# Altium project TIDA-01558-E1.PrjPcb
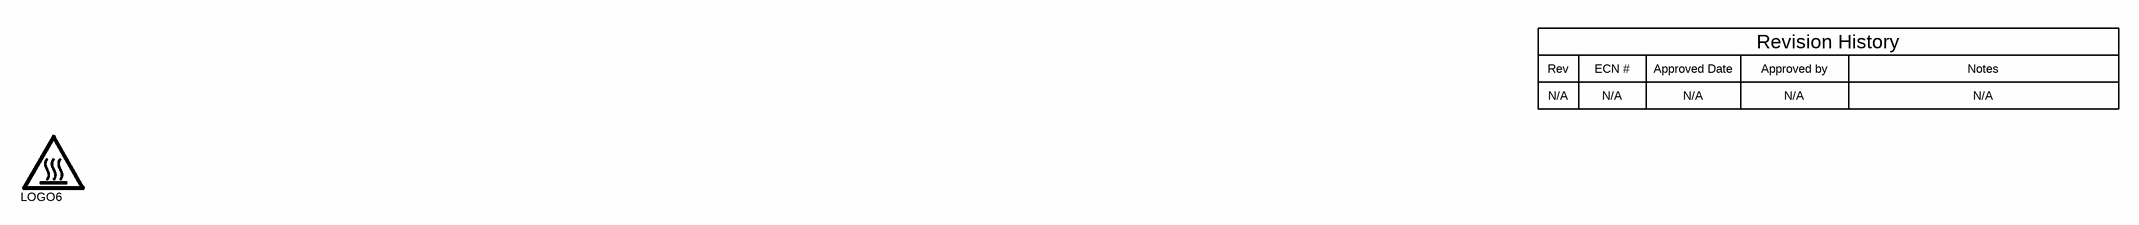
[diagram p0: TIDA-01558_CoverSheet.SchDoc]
CopyrightYear: 2017; EVM_Orderable: N/A; PCB_Layout: Akshay Labhe; PCB_Rev: E1; PRJ_Customer: Public Release; PRJ_Engineer: Neha Nain; PRJ_Number: TIDA-01558; PRJ_Title: 500W Buck Boost; SCH_Rev: E1; TechSupport: http://www.ti.com/support; TID: TIDA-01558
3 sheets, 86 parts. Net scope: flat (ports and power ports of the same name join across sheets).
Board file: TIDA-01558_PCB.PcbDoc
Sheets:
  TIDA-01558_CoverSheet.SchDoc
  TIDA-01558_Sheet1.SchDoc
  TIDA-01558_Hardware.SchDoc

## Sheet TIDA-01558_CoverSheet.SchDoc: Cover Sheet
size 431 x 279 mm; Date: Not shown in title block; ApprovedBy: Not shown in title block; CheckedBy: Not shown in title block; Author: Not shown in title block; CompanyName: Not shown in title block; DrawnBy: Neha Nain; Engineer: Not shown in title block; Organization: Not shown in title block; Address1: Not shown in title block; Address2: Not shown in title block; Address3: Not shown in title block; Address4: Not shown in title block; DocumentNumber: 1; Revision: Use project parameter SCH_Rev; SheetNumber: 1; SheetTotal: 3; PageSetup: Record=PageOptions¦CenterHorizontal=True¦CenterVertical=True¦PrintScale=1.00¦XCorrection=1.00¦YCorrection=1.00¦PrintKind=0¦BorderSize=5000000¦LeftOffset=0¦BottomOffset=0¦Orientation=2¦PaperLength=1000¦PaperWidth=1000¦Scale=100¦PaperSource=15¦PrintQuality=600¦MediaType=1¦DitherType=10¦PaperKind=Letter¦PrintScaleMode=1

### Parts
(Parts that share a designator on the sheet are numbered #1, #2 ... from top to bottom, then left to right.)
LOGO6#1  CAUTION HOT SURFACE  [IEC_HotSurface_Small]  (value not drawn)  (no BOM)

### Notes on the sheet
- Rev
- N/A
- ECN #
- Approved Date
- Approved by
- Revision History
- Notes

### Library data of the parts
LOGO6#1 = IEC_HotSurface: IEC 61010-1 Hot Surface Warning; SymbolCreator: a0412235

## Sheet TIDA-01558_Sheet1.SchDoc: Sheet1
size 431 x 279 mm; Date: Not shown in title block; ApprovedBy: Not shown in title block; CheckedBy: Not shown in title block; Author: Not shown in title block; CompanyName: Not shown in title block; DrawnBy: Neha Nain; Engineer: Not shown in title block; Organization: Not shown in title block; Address1: Not shown in title block; Address2: Not shown in title block; Address3: Not shown in title block; Address4: Not shown in title block; DocumentNumber: 1; Revision: Use project parameter SCH_Rev; SheetNumber: 2; SheetTotal: 3; PageSetup: Record=PageOptions¦CenterHorizontal=True¦CenterVertical=True¦PrintScale=1.00¦XCorrection=1.00¦YCorrection=1.00¦PrintKind=0¦BorderSize=5000000¦LeftOffset=0¦BottomOffset=0¦Orientation=2¦PaperLength=1000¦PaperWidth=1000¦Scale=100¦PaperSource=15¦PrintQuality=600¦MediaType=1¦DitherType=10¦PaperKind=Letter¦PrintScaleMode=1
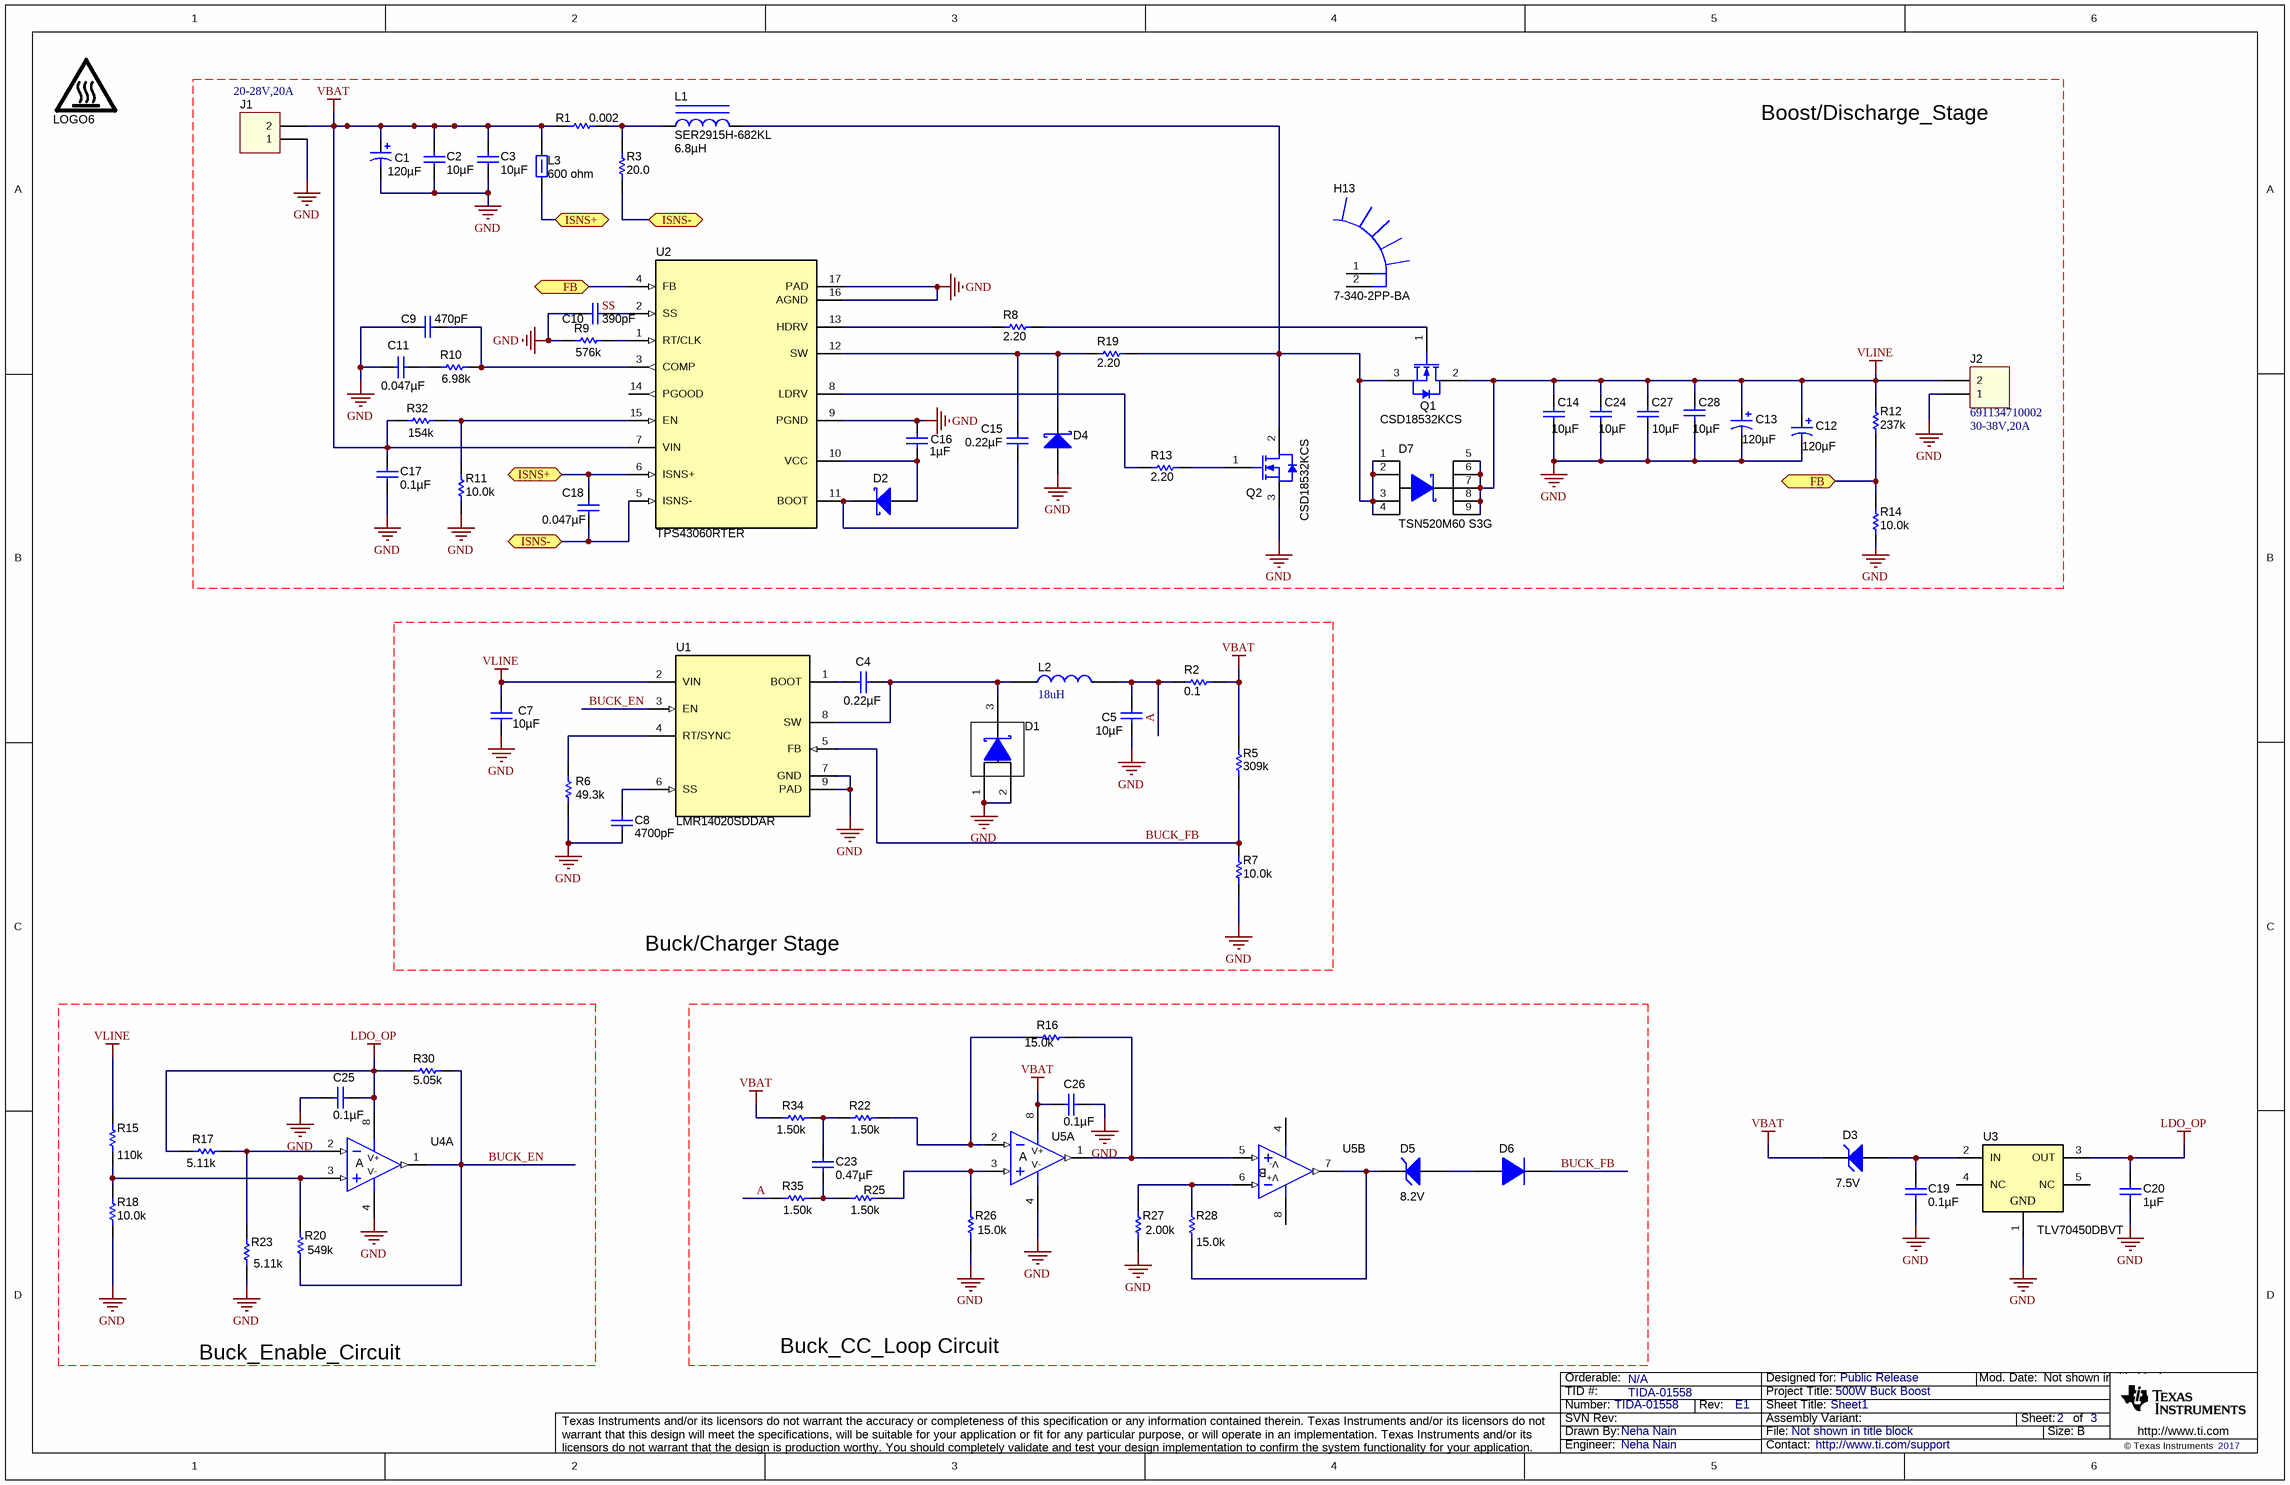
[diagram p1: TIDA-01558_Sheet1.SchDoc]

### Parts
(Parts that share a designator on the sheet are numbered #1, #2 ... from top to bottom, then left to right.)
C1  ValueDisplayed: 120µF  [Chemi-Con_800x1150]  (hidden comment: 127AVG050MFBJ)
C2  ValueDisplayed: 10µF  [1210_280]  (hidden comment: C3225X7R1H106M250AC)
C3  ValueDisplayed: 10µF  [1210_280]  (hidden comment: C3225X7R1H106M250AC)
C4  ValueDisplayed: 0.22µF  [0603]  (hidden comment: 06033D224KAT2A)
C5  ValueDisplayed: 10µF  [1210_280]  (hidden comment: C3225X7R1H106M250AC)
C7  ValueDisplayed: 10µF  [1210_280]  (hidden comment: C3225X7R1H106M250AC)
C8  ValueDisplayed: 4700pF  [0603]  (hidden comment: GRM188R71E472KA01D)
C9  ValueDisplayed: 470pF  [0603]  (hidden comment: C0603C471K3RACTU)
C10  ValueDisplayed: 390pF  [0603]  (hidden comment: 06035A391JAT2A)
C11  ValueDisplayed: 0.047µF  [0603]  (hidden comment: 06033C473JAT2A)
C12  ValueDisplayed: 120µF  [Chemi-Con_800x1150]  (hidden comment: 127AVG050MFBJ)
C13  ValueDisplayed: 120µF  [Chemi-Con_800x1150]  (hidden comment: 127AVG050MFBJ)
C14  ValueDisplayed: 10µF  [1210_280]  (hidden comment: C3225X7R1H106M250AC)
C15  ValueDisplayed: 0.22µF  [0603]  (hidden comment: 06033D224KAT2A)
C16  ValueDisplayed: 1µF  [0603]  (hidden comment: 06033C105KAT2A)
C17  ValueDisplayed: 0.1µF  [0603]  (hidden comment: 06035C104KAT2A)
C18  ValueDisplayed: 0.047µF  [1206]  (hidden comment: GRM31M5C1H473JA01L)
C19  ValueDisplayed: 0.1µF  [0603]  (hidden comment: 06035C104KAT2A)
C20  ValueDisplayed: 1µF  [0603]  (hidden comment: 06033C105KAT2A)
C23  ValueDisplayed: 0.47µF  [0603]  (hidden comment: GRM188R71E474KA12D)
C24  ValueDisplayed: 10µF  [1210_280]  (hidden comment: C3225X7R1H106M250AC)
C25  ValueDisplayed: 0.1µF  [0603]  (hidden comment: 06033C104KAT2A)
C26  ValueDisplayed: 0.1µF  [0603]  (hidden comment: 06033C104KAT2A)
C27  ValueDisplayed: 10µF  [1210_280]  (hidden comment: C3225X7R1H106M250AC)
C28  ValueDisplayed: 10µF  [1210_280]  (hidden comment: C3225X7R1H106M250AC)
D1  MBR10U60-TP  [TO-277A]  (value not drawn)
D2  PMEG6010CEJ,115  [SOD-323F]  (value not drawn)
D3  value 7.5V  [SMA]  (hidden comment: SMAJ5922B-TP)
D4  PMEG6010CEJ,115  [SOD-323F]  (value not drawn)
D5  value 8.2V  [SOD-323]  (hidden comment: MM3Z8V2T1G)
D6  1N4448WX-TP  [SOD-323]  (value not drawn)
D7  TSN520M60 S3G  [PDFN56]
H13  7-340-2PP-BA  [HEATSINK_7-340-2PP]
J1  691134710002  [691134710002]  (value not drawn)
J2  691134710002  [691134710002]
L1  SER2915H-682KL  ValueDisplayed: 6.8µH  [SER2915]
L2  value 18uH  [IND_RLB9012]  (hidden comment: RLB9012-180KL)
L3  ValueDisplayed: 600 ohm  [0603]  (hidden comment: BLM18KG601SN1D)
LOGO6#2  CAUTION HOT SURFACE  [IEC_HotSurface_Small]  (value not drawn)  (no BOM)
Q1  CSD18532KCS  [TO-220AB_Horizontal_100mil]
Q2  CSD18532KCS  [TO-220AB_Horizontal_100mil]
R1  ValueDisplayed: 0.002  [2512]  (hidden comment: CRE2512-FZ-R002E-3)
R2  ValueDisplayed: 0.1  [1206]  (hidden comment: CRM1206-FX-R100ELF)
R3  ValueDisplayed: 20.0  [0603]  (hidden comment: RC0603FR-0720RL)
R5  ValueDisplayed: 309k  [0603]  (hidden comment: RT0603BRD07309KL)
R6  ValueDisplayed: 49.3k  [0603]  (hidden comment: RT0603DRE0749K3L)
R7  ValueDisplayed: 10.0k  [0603]  (hidden comment: ERJ-3EKF1002V)
R8  ValueDisplayed: 2.20  [0805_HV1]  (hidden comment: RC0805FR-072R2L)
R9  ValueDisplayed: 576k  [0603]  (hidden comment: RT0603DRE07576KL)
R10  ValueDisplayed: 6.98k  [0603]  (hidden comment: RT0603DRE076K98L)
R11  ValueDisplayed: 10.0k  [0603]  (hidden comment: ERJ-3EKF1002V)
R12  ValueDisplayed: 237k  [0603]  (hidden comment: RT0603BRD07237KL)
R13  ValueDisplayed: 2.20  [1206]  (hidden comment: ERJ-8RQF2R2V)
R14  ValueDisplayed: 10.0k  [0603]  (hidden comment: ERJ-3EKF1002V)
R15  ValueDisplayed: 110k  [0603]  (hidden comment: RT0603DRE07110KL)
R16  ValueDisplayed: 15.0k  [0603]  (hidden comment: RT0603BRD0715KL)
R17  ValueDisplayed: 5.11k  [0603]  (hidden comment: RG1608P-5111-B-T5)
R18  ValueDisplayed: 10.0k  [0603]  (hidden comment: ERJ-3EKF1002V)
R19  ValueDisplayed: 2.20  [0805_HV1]  (hidden comment: RC0805FR-072R2L)
R20  ValueDisplayed: 549k  [0603]  (hidden comment: RC0603FR-07549KL)
R22  ValueDisplayed: 1.50k  [0603]  (hidden comment: RT0603BRD071K5L)
R23  ValueDisplayed: 5.11k  [0603]  (hidden comment: RG1608P-5111-B-T5)
R25  ValueDisplayed: 1.50k  [0603]  (hidden comment: RT0603BRD071K5L)
R26  ValueDisplayed: 15.0k  [0603]  (hidden comment: RT0603BRD0715KL)
R27  ValueDisplayed: 2.00k  [0603]  (hidden comment: RT0603BRD072KL)
R28  ValueDisplayed: 15.0k  [0603]  (hidden comment: RT0603BRD0715KL)
R30  ValueDisplayed: 5.05k  [0603]  (hidden comment: RT0603BRD075K05L)
R32  ValueDisplayed: 154k  [0603]  (hidden comment: RT0603DRE07154KL)
R34  ValueDisplayed: 1.50k  [0603]  (hidden comment: RT0603BRD071K5L)
R35  ValueDisplayed: 1.50k  [0603]  (hidden comment: RT0603BRD071K5L)
U1  LMR14020SDDAR  [DDA0008E_N]
U2  TPS43060RTER  [RTE0016E]
U3  TLV70450DBVT  [DBV0005A_N]
U4  LM293AD  [D0008A_N]  (value not drawn)  (part A of 2)
U5  LM358AD  [D0008A_N]  (value not drawn)  (parts A,B of 2)

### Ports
FB, ISNS+, ISNS-

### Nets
GND: C1.2(-) C2.2 C3.2 C5.2 C7.2 C8.2 C9.2 C10.2 C11.2 C12.2(-) C13.2(-) C14.2 C16.1 C17.2 C19.2 C20.2 C24.2 C25.2 C26.2 C27.2 C28.2 D1.1(A) D1.2(A) D4.2(A) J1.1 J2.1 Q2.3(S) R6.1 R7.1 R9.1 R11.1 R14.1 R18.1 R23.1 R26.1 R27.1 U1.7(GND) U1.9(PAD) U2.9(PGND) U2.16(AGND) U2.17(PAD) U3.1(GND) U4.4(V-) U5.4(V-)
LDO_OP: C20.1 C25.1 R17.1 R30.1 U3.3(OUT) U4.8(V+)
VBAT: C1.1(+) C2.1 C3.1 C17.1 C26.1 D3.1(K) J1.2 L3.2 R1.1 R2.2 R5.2 R32.1 R34.1 U2.7(VIN) U5.8(V+)
VLINE: C7.1 C12.1(+) C13.1(+) C14.1 C24.1 C27.1 C28.1 D7.5(C) D7.6(C) D7.7(C) D7.8(C) D7.9(C) J2.2 Q1.2(D) R12.2 R15.2 U1.2(VIN)
A: C5.1 L2.2 R2.1 R35.1
BUCK_EN: R20.1 R30.2 U1.3(EN) U4.1(OUT)
BUCK_FB: D6.1(K) R5.1 R7.2 U1.5(FB)
FB: R12.1 R14.2 U2.4(FB) ; port FB
ISNS+: C18.1 L3.1 U2.6(ISNS+) ; port ISNS+
ISNS-: C18.2 R3.1 U2.5(ISNS-) ; port ISNS-
NetC4_1: C4.1 U1.1(BOOT)
NetC4_2: C4.2 D1.3(K) L2.1 U1.8(SW)
NetC8_1: C8.1 U1.6(SS)
NetC9_1: C9.1 R10.2 U2.3(COMP)
NetC10_1: C10.1 U2.2(SS)
NetC11_1: C11.1 R10.1
NetC15_1: C15.1 D4.1(K) R19.1 U2.12(SW)
NetC15_2: C15.2 D2.1(K) U2.11(BOOT)
NetC16_2: C16.2 D2.2(A) U2.10(VCC)
NetC19_1: C19.1 D3.2(A) U3.2(IN)
NetC23_1: C23.1 R22.1 R34.2
NetC23_2: C23.2 R25.1 R35.2
NetD5_1: D5.1(K) R28.2 U5.7(OUT)
NetD5_2: D5.2(A) D6.2(A)
NetD7_1: D7.1(A) D7.2(A) D7.3(A) D7.4(A) L1.2 Q1.3(S) Q2.2(D) R19.2
NetL1_1: L1.1 R1.2 R3.2
NetQ1_1: Q1.1(G) R8.2
NetQ2_1: Q2.1(G) R13.2
NetR6_2: R6.2 U1.4(RT/SYNC)
NetR8_1: R8.1 U2.13(HDRV)
NetR9_2: R9.2 U2.1(RT/CLK)
NetR11_2: R11.2 R32.2 U2.15(EN)
NetR13_1: R13.1 U2.8(LDRV)
NetR15_1: R15.1 R18.2 R20.2 U4.3(IN+)
NetR16_1: R16.1 R22.2 U5.2(IN-)
NetR16_2: R16.2 U5.1(OUT) U5.5(IN+)
NetR17_2: R17.2 R23.2 U4.2(IN-)
NetR25_2: R25.2 R26.2 U5.3(IN+)
NetR27_2: R27.2 R28.1 U5.6(IN-)

Not connected (* = marked no-connect by the designer): H13 1 2; U2 14(PGOOD); U3 4(NC) 5(NC)

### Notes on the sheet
- (near J1) 20-28V,20A
- Boost/Discharge_Stage
- (near J2) 30-38V,20A
- Buck/Charger Stage
- Buck_Enable_Circuit
- Buck_CC_Loop Circuit
- Labels drawn without touching a wire or pin: SS

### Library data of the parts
C1 C12 C13 = EKMG500ELL101MHB5D: CAP, AL, 120 µF, 50 V, +/- 20%, TH; Manufacturer: Illinois Capacitor; Polarized: Y; CompType: Capacitor; Value: 120uF; U/M: EA; Cap_F: 0.0001; Tolerance_%: 20; VDC_V: 50; Value2: 50V; IRMS_A: 0.18; TaMin_C: -55; TaMax_C: 105; Cap_Case: 8x11.5mm; SizeAreaWB_mm2: 100; SizeArea_mm2: 64; SizeX_mm: 8; SizeZ_mm: 13; AEC Category: Q200; AEC Qualified: N
C2 C3 C5 C7 C14 C24 C27 C28 = C3225X7R1H106M250AC: CAP, CERM, 10 µF, 50 V,+/- 20%, X7R, 1210; Manufacturer: TDK; Polarized: N; CompType: Capacitor; Value: 10uF; U/M: EA; Cap_F: 0.00001; Tolerance_%: 20; VDC_V: 50; Value2: 50V; TaMin_C: -55; TaMax_C: 125; Cap_Case: 1210; SizeArea_mm2: 8; SizeAreaWB_mm2: 14.7; SizeX_mm: 3.2; SizeY_mm: 2.5; SizeZ_mm: 2.8; AEC Category: Q200; Green_Lifecycle: Active; Green_REACh: Passed
C4 C15 = 06033D224KAT2A: CAP, CERM, 0.22 µF, 25 V,+/- 10%, X5R, 0603; Manufacturer: AVX; Polarized: N; CompType: Capacitor; Value: 0.22uF; U/M: EA; Cap_F: 0.00000022; Tolerance_%: 10; ESR_ohm: 0.036; Value1: 0.036 ohm; VDC_V: 25; Value2: 25V; TaMin_C: -55; TaMax_C: 85; SizeArea_mm2: 1.28; SizeAreaWB_mm2: 4.68; SizeX_mm: 1.6; SizeY_mm: 0.8; SizeZ_mm: 1; AEC Category: Q200; Green_Lifecycle: Active; Green_REACh: Passed
C8 = GRM188R71E472KA01D: CAP, CERM, 4700 pF, 25 V,+/- 10%, X7R, 0603; Manufacturer: MuRata; Polarized: N; CompType: Capacitor; Value: 4700pF; U/M: EA; Cap_F: 0.0000000047; Tolerance_%: 10; VDC_V: 25; Value2: 25V; TaMin_C: -55; TaMax_C: 125; SizeArea_mm2: 1.28; SizeAreaWB_mm2: 4.68; SizeX_mm: 1.6; SizeY_mm: 0.8; SizeZ_mm: 1; AEC Category: Q200
C9 = C0603C471K5RACTU: CAP, CERM, 470 pF, 25 V,+/- 10%, X7R, 0603; Manufacturer: Kemet; Polarized: N; CompType: Capacitor; Value: 470pF; U/M: EA; Cap_F: 0.00000000047; Tolerance_%: 10; VDC_V: 25; Value2: 25V; TaMin_C: -55; TaMax_C: 125; SizeArea_mm2: 1.28; SizeAreaWB_mm2: 4.68; SizeX_mm: 1.6; SizeY_mm: 0.8; SizeZ_mm: 1; AEC Category: Q200; Green_Lifecycle: Active; Green_REACh: Passed
C10 = 06035A391JAT2A: CAP, CERM, 390 pF, 50 V,+/- 5%, C0G/NP0, 0603; Manufacturer: AVX; Polarized: N; CompType: Capacitor; Value: 390pF; U/M: EA; Cap_F: 0.00000000039; Tolerance_%: 5; ESR_ohm: 0.067; Value1: 0.067 ohm; VDC_V: 50; Value2: 50V; TaMin_C: -55; TaMax_C: 125; SizeArea_mm2: 1.28; SizeAreaWB_mm2: 4.68; SizeX_mm: 1.6; SizeY_mm: 0.8; SizeZ_mm: 1; AEC Category: Q200; Green_Lifecycle: Not Set; Green_REACh: Incomplete
C11 = 06033C473JAT2A: CAP, CERM, 0.047 µF, 25 V,+/- 5%, X7R, 0603; Manufacturer: AVX; Polarized: N; CompType: Capacitor; Value: 0.047uF; U/M: EA; Cap_F: 0.000000047; Tolerance_%: 5; ESR_ohm: 0.052; Value1: 0.052 ohm; VDC_V: 25; Value2: 25V; TaMin_C: -55; TaMax_C: 125; SizeArea_mm2: 1.28; SizeAreaWB_mm2: 4.68; SizeX_mm: 1.6; SizeY_mm: 0.8; SizeZ_mm: 1; AEC Category: Q200; Green_Lifecycle: Active; Green_REACh: Passed
C16 C20 = 06033C105KAT2A: CAP, CERM, 1 µF, 25 V,+/- 10%, X7R, 0603; Manufacturer: AVX; Polarized: N; CompType: Capacitor; Value: 1uF; U/M: EA; Cap_F: 0.000001; Tolerance_%: 10; Value1: Unknown; VDC_V: 25; Value2: 25V; TaMin_C: -55; TaMax_C: 125; SizeArea_mm2: 1.28; SizeAreaWB_mm2: 4.68; SizeX_mm: 1.6; SizeY_mm: 0.8; SizeZ_mm: 1; AEC Category: Q200
C17 C19 = 06035C104KAT2A: CAP, CERM, 0.1 µF, 50 V,+/- 10%, X7R, 0603; Manufacturer: AVX; Polarized: N; CompType: Capacitor; Value: 0.1uF; U/M: EA; Cap_F: 0.0000001; Tolerance_%: 10; VDC_V: 50; Value2: 50V; TaMin_C: -55; TaMax_C: 125; SizeArea_mm2: 1.28; SizeAreaWB_mm2: 4.68; SizeX_mm: 1.6; SizeY_mm: 0.8; SizeZ_mm: 1; AEC Category: Q200; Green_Lifecycle: Active; Green_REACh: Passed
C18 = GRM31M5C1H473JA01L: CAP, CERM, 0.047 µF, 50 V,+/- 5%, C0G/NP0, 1206; Manufacturer: MuRata; Polarized: N; CompType: Capacitor; Value: 0.047uF; U/M: EA; Cap_F: 0.000000047; Tolerance_%: 5; VDC_V: 50; Value2: 50V; TaMin_C: -55; TaMax_C: 125; SizeArea_mm2: 5.12; SizeAreaWB_mm2: 10.92; SizeX_mm: 3.2; SizeY_mm: 1.6; SizeZ_mm: 1.35; AEC Category: Q200; Green_Lifecycle: Active; Green_REACh: Passed
C23 = GRM188R71E474KA12D: CAP, CERM, 0.47 µF, 25 V,+/- 10%, X7R, 0603; Manufacturer: MuRata; Polarized: N; CompType: Capacitor; Value: 0.47uF; U/M: EA; Cap_F: 0.00000047; Tolerance_%: 10; VDC_V: 25; Value2: 25V; TaMin_C: -55; TaMax_C: 125; SizeArea_mm2: 1.28; SizeAreaWB_mm2: 4.68; SizeX_mm: 1.6; SizeY_mm: 0.8; SizeZ_mm: 1; AEC Category: Q200; Green_Lifecycle: Active; Green_REACh: Passed
C25 C26 = 06033C104KAT2A: CAP, CERM, 0.1 µF, 25 V,+/- 10%, X7R, 0603; Manufacturer: AVX; Polarized: N; CompType: Capacitor; Value: 0.1uF; U/M: EA; Cap_F: 0.0000001; Tolerance_%: 10; ESR_ohm: 0.05; Value1: 0.05 ohm; VDC_V: 25; Value2: 25V; TaMin_C: -55; TaMax_C: 125; SizeArea_mm2: 1.28; SizeAreaWB_mm2: 4.68; SizeX_mm: 1.6; SizeY_mm: 0.8; SizeZ_mm: 1; AEC Category: Q200; Green_Lifecycle: Active; Green_REACh: Passed
D1 = FSV10100V: DIODE SCHOTTKY 60V 10A TO277; Manufacturer: Micro Commercial Co; U/M: EA; Vf_V: 500mV; Io_A: 10; TJmax_C: 150; SizeAreaWB_mm2: 57.375; SizeArea_mm2: 30.875; SizeX_mm: 6.5; SizeY_mm: 4.75; SizeZ_mm: 1.2; AEC Category: Q101; AEC Qualified: Y; Green_Lifecycle: Not Set; Green_REACh: Incomplete
D2 D4 = PMEG6010CEJ,115: Diode, Schottky, 60 V, 1 A, SOD-323F; Manufacturer: Nexperia; U/M: EA; Vf_V: 0.66; Value: 60V; Value1: 1A; Value2: 0.66V; Io_A: 1; Vr_V: 60; TJmax_C: 150; SizeAreaWB_mm2: 7.875; SizeArea_mm2: 3.125; SizeX_mm: 2.5; SizeY_mm: 1.25; SizeZ_mm: 0.8; AEC Category: Q101; Green_Lifecycle: Not Set; Green_REACh: Incomplete
D3 = SMAZ30-13-F: DIODE ZENER 7.5V 1.5W DO214AC; Manufacturer: Micro Commercial Co; SymbolCreator: a0412235; U/M: EA; Power_W: 1; RJA_CperW: 100; SizeAreaWB_mm2: 37.3428; SizeArea_mm2: 16.3228; SizeX_mm: 5.59; SizeY_mm: 2.92; SizeZ_mm: 2.87; AEC Category: Q101; AEC Qualified: N
D5 = MMSZ5238BS-7-F: Diode, Zener, 8.7 V, 200 mW, SOD-323; Manufacturer: On Semi; SymbolCreator: a0412235; U/M: EA; Power_W: 0.2; Vz_V: 8.2; Value1: 0.3W; RJA_CperW: 350; SizeAreaWB_mm2: 8.695; SizeArea_mm2: 3.645; SizeX_mm: 2.7; SizeY_mm: 1.35; SizeZ_mm: 1; AEC Category: Q101
D6 = 1N4448WX-TP: Diode, Switching, 75 V, 0.25 A, SOD-323; Manufacturer: Micro Commercial Components; U/M: EA; Value: 75V; Value1: 0.25A; Io_A: 0.25; Vr_V: 75; TJmax_C: 150; SizeAreaWB_mm2: 8.695; SizeArea_mm2: 3.645; SizeX_mm: 2.7; SizeY_mm: 1.35; SizeZ_mm: 1; AEC Category: Q101; Green_Lifecycle: Not Set; Green_REACh: Incomplete
D7 = CMP-0078759-1: Diode, Schottky, 60 V, 20 A, AEC-Q101, PDFN56; Manufacturer: Taiwan Semiconductor; SizeAreaWB_mm2: 59.04; Vr_V: 60V; SizeArea_mm2: 32.24; AEC Qualified: Y; TJmax_C: 150°C; AEC Category: Q101; Value: 60V; SizeZ_mm: 1.25; Io_A: 20A; Vf_V: 5.8dV; SizeY_mm: 5.2; Value2: 0.58V; SizeX_mm: 6.2
H13 = 7-345-2PP-BA: Heatsink, TO-220, Black Anodized; Manufacturer: CTS Thermal Management Products; SymbolCreator: a0799628
J1 J2 = 691134710002: WR-TBL Serie 1347 - 5.00 mm Horizontal Cable Entry with Pressure Clamp, 02p; Manufacturer: Wurth Elektronik; Pitch: 5 mm
L1 = SER2915H-682KL: Inductor, Shielded E Core, Ferrite, 6.8uH, 30A, 0.00186 ohm, SMD; Manufacturer: Coilcraft; Ind_H: 6.8E-6; Imax_A: 30; Irms: 30A @ 40C rise; Isat: 36.2A @ 30% inductance drop; U/M: EA
L2 = RLB9012-180KL: INDUCTOR, FIXED, 18uH, 10%, 2.66A, 11MHz, TH, 2-PIN; Manufacturer: BOURNS; SymbolCreator: x0199378
L3 = BLM18KG601SN1D: Ferrite Bead, 600 ohm @ 100 MHz, 1.3 A, 0603; Manufacturer: MuRata; Value: 600 ohm; Imax_A: 1.3; DCR_ohm: 0.15; Value1: 0.15 ohm; Value2: 1.3A; SizeAreaWB_mm2: 4.68; SizeArea_mm2: 1.28; SizeX_mm: 1.6; SizeY_mm: 0.8; SizeZ_mm: 1; ZTyp@100MHz_Ohm: 600; Green_Lifecycle: Active; Green_REACh: Passed
LOGO6#2 = IEC_HotSurface: as LOGO6#1 on sheet TIDA-01558_CoverSheet
Q1 Q2 = CSD18532KCS: MOSFET, N-CH, 60 V, 100 A, KCS0003B (TO-220-3); Manufacturer: Texas Instruments; Alternate Manufacturer: None; U/M: EA; ChType: N; Value: 60V; VdsMax_V: 60; Value1: 0.0053 ohm; Rdson45_ohm: 0.0053; Value2: 44 nC; QgTyp_nC: 44; Vgs_V: 20; IdsMax_A: 100; SizeAreaWB_mm2: 79.648; SizeArea_mm2: 46.228; SizeX_mm: 4.55; SizeY_mm: 10.16; SizeZ_mm: 20.45; AEC Category: Q101
R1 = ERJ-M1WTF2M0U: RES SMD 2 MOHM 1% 3W 2512; Manufacturer: Bourns Inc.; CompType: Resistor; Value: 0.002; Value_Code: 2L000; Tolerance_%: 1; TempCo: ppm/C; SizeArea_mm2: 20.16; SizeX_mm: 6.3; SizeY_mm: 3.2; SizeZ_mm: 0.71; U/M: EA; AEC Category: Q200
R2 = CRM1206-FX-R100ELF: RES, 0.1, 1%, 0.5 W, 1206; Manufacturer: Bourns; CompType: Resistor; Value: 0.1; Value_Code: R100; Tolerance_%: 1; Power_W: 0.5; Value2: 0.5W; VDC_V: 0; TempCo: 150 ppm/C; SizeArea_mm2: 5.12; SizeX_mm: 3.2; SizeY_mm: 1.6; SizeZ_mm: 1.35; EIA_Code: E96; U/M: EA; AEC Category: Q200
R3 = RC0603FR-0720RL: RES, 20.0, 1%, 0.1 W, 0603; Manufacturer: Yageo America; CompType: Resistor; Value: 20.0; Res_ohm: 20; Value_Code: 20R0; Tolerance_%: 1; Power_W: 0.1; Value2: 0.1W; VDC_V: 150; TempCo: 200 ppm/C; SizeArea_mm2: 1.28; SizeX_mm: 1.6; SizeY_mm: 0.8; EIA_Code: E96; U/M: EA; AEC Category: Q200; Green_Lifecycle: Active; Green_REACh: Passed
R5 = RT0603BRD07309KL: RES, 309 k, 0.1%, 0.1 W, 0603; Manufacturer: Yageo America; CompType: Resistor; Value: 309k; Res_ohm: 309000; Tolerance_%: 0.1; Value2: 0.1W; VDC_V: 75; TempCo: 25 ppm/C; SizeArea_mm2: 1.28; SizeX_mm: 1.6; SizeY_mm: 0.8; SizeZ_mm: 1; EIA_Code: E192; U/M: EA; AEC Category: Q200
R6 = RT0603DRE0749K3L: RES, 49.3 k, 0.5%, 0.1 W, 0603; Manufacturer: Yageo America; CompType: Resistor; Value: 49.3k; Res_ohm: 49300; Value_Code: 49k3; Tolerance_%: 0.5; Power_W: 0.1; Value2: 0.1W; VDC_V: 75; TempCo: 50 ppm/C; SizeArea_mm2: 1.28; SizeX_mm: 1.6; SizeY_mm: 0.8; SizeZ_mm: 1; EIA_Code: E192; U/M: EA; AEC Category: Q200
R7 R11 R14 R18 = ERJ-3EKF1002V: RES, 10.0 k, 1%, 0.1 W, 0603; Manufacturer: Panasonic; CompType: Resistor; Value: 10.0k; Res_ohm: 10000; Value_Code: 10k0; Tolerance_%: 1; Power_W: 0.1; Value2: 0.1W; VDC_V: 75; TempCo: 100 ppm/C; SizeArea_mm2: 1.28; SizeX_mm: 1.6; SizeY_mm: 0.8; EIA_Code: E96; U/M: EA; AEC Category: Q200; Green_Lifecycle: Active; Green_REACh: Passed
R8 R19 = RC0805FR-072R2L: RES, 2.20, 1%, 0.125 W, 0805; Manufacturer: Yageo America; CompType: Resistor; Value: 2.20; Res_ohm: 2.2; Value_Code: 2R20; Tolerance_%: 1; Power_W: 0.125; Value2: 0.125W; VDC_V: 150; TempCo: 200 ppm/C; SizeArea_mm2: 2.5; SizeX_mm: 2; SizeY_mm: 1.25; SizeZ_mm: 1.45; U/M: EA; AEC Category: Q200; Green_Lifecycle: Active; Green_REACh: Passed
R9 = RT0603DRE07576KL: RES, 576 k, 0.5%, 0.1 W, 0603; Manufacturer: Yageo America; CompType: Resistor; Value: 576k; Res_ohm: 576000; Tolerance_%: 0.5; Power_W: 0.1; Value2: 0.1W; VDC_V: 75; TempCo: 50 ppm/C; SizeArea_mm2: 1.28; SizeX_mm: 1.6; SizeY_mm: 0.8; SizeZ_mm: 1; EIA_Code: E192; U/M: EA; AEC Category: Q200
R10 = RT0603DRE076K98L: RES, 6.98 k, 0.5%, 0.1 W, 0603; Manufacturer: Yageo America; CompType: Resistor; Value: 6.98k; Res_ohm: 6980; Value_Code: 6k98; Tolerance_%: 0.5; Power_W: 0.1; Value2: 0.1W; VDC_V: 75; TempCo: 50 ppm/C; SizeArea_mm2: 1.28; SizeX_mm: 1.6; SizeY_mm: 0.8; SizeZ_mm: 1; EIA_Code: E192; U/M: EA; AEC Category: Q200
R12 = RT0603BRD07237KL: RES, 237 k, 0.1%, 0.1 W, 0603; Manufacturer: Yageo America; CompType: Resistor; Value: 237k; Res_ohm: 237000; Tolerance_%: 0.1; Value2: 0.1W; VDC_V: 75; TempCo: 25 ppm/C; SizeArea_mm2: 1.28; SizeX_mm: 1.6; SizeY_mm: 0.8; SizeZ_mm: 1; EIA_Code: E192; U/M: EA; AEC Category: Q200
R13 = ERJ-8RQF2R2V: RES, 2.20, 1%, 0.25 W, 1206; Manufacturer: Panasonic; CompType: Resistor; Value: 2.20; Res_ohm: 2.2; Value_Code: 2R20; Tolerance_%: 1; Power_W: 0.25; Value2: 0.25W; TempCo: 200 ppm/C; SizeArea_mm2: 5.12; SizeX_mm: 3.2; SizeY_mm: 1.6; SizeZ_mm: 1.35; U/M: EA; AEC Category: Q200; Green_Lifecycle: Active; Green_REACh: Passed
R15 = RT0603DRE07110KL: RES, 110 k, 0.5%, 0.1 W, 0603; Manufacturer: Yageo America; CompType: Resistor; Value: 110k; Res_ohm: 110000; Tolerance_%: 0.5; Power_W: 0.1; Value2: 0.1W; VDC_V: 75; TempCo: 50 ppm/C; SizeArea_mm2: 1.28; SizeX_mm: 1.6; SizeY_mm: 0.8; SizeZ_mm: 1; EIA_Code: E192; U/M: EA; AEC Category: Q200
R16 R26 R28 = RT0603BRD0715KL: RES, 15.0 k, 0.1%, 0.1 W, 0603; Manufacturer: Yageo America; CompType: Resistor; Value: 15.0k; Res_ohm: 15000; Value_Code: 15k0; Tolerance_%: 0.1; Value2: 0.1W; VDC_V: 75; TempCo: 25 ppm/C; SizeArea_mm2: 1.28; SizeX_mm: 1.6; SizeY_mm: 0.8; SizeZ_mm: 1; EIA_Code: E192; U/M: EA; AEC Category: Q200; Green_Lifecycle: Active; Green_REACh: Passed
R17 R23 = RG1608P-5111-B-T5: RES, 5.11 k, 0.1%, 0.1 W, 0603; Manufacturer: Susumu Co Ltd; CompType: Resistor; Value: 5.11k; Res_ohm: 5110; Value_Code: 5k11; Tolerance_%: 0.1; Value2: 0.1W; VDC_V: 75; TempCo: 25 ppm/C; SizeArea_mm2: 1.28; SizeX_mm: 1.6; SizeY_mm: 0.8; SizeZ_mm: 1; EIA_Code: E192; U/M: EA; AEC Category: Q200
R20 = RC0603FR-07549KL: RES, 549 k, 1%, 0.1 W, 0603; Manufacturer: Yageo America; CompType: Resistor; Value: 549k; Res_ohm: 549000; Tolerance_%: 1; Power_W: 0.1; Value2: 0.1W; VDC_V: 150; TempCo: 200 ppm/C; SizeArea_mm2: 1.28; SizeX_mm: 1.6; SizeY_mm: 0.8; EIA_Code: E96; U/M: EA; AEC Category: Q200; Green_Lifecycle: Active; Green_REACh: Passed
R22 R25 R34 R35 = RT0603BRD071K5L: RES, 1.50 k, 0.1%, 0.1 W, 0603; Manufacturer: Yageo America; CompType: Resistor; Value: 1.50k; Res_ohm: 1500; Value_Code: 1k50; Tolerance_%: 0.1; Value2: 0.1W; VDC_V: 75; TempCo: 25 ppm/C; SizeArea_mm2: 1.28; SizeX_mm: 1.6; SizeY_mm: 0.8; SizeZ_mm: 1; EIA_Code: E192; U/M: EA; AEC Category: Q200
R27 = RT0603BRD072KL: RES, 2.00 k, 0.1%, 0.1 W, 0603; Manufacturer: Yageo America; CompType: Resistor; Value: 2.00k; Res_ohm: 2000; Value_Code: 2k00; Tolerance_%: 0.1; Value2: 0.1W; VDC_V: 75; TempCo: 25 ppm/C; SizeArea_mm2: 1.28; SizeX_mm: 1.6; SizeY_mm: 0.8; SizeZ_mm: 1; EIA_Code: E192; U/M: EA; AEC Category: Q200
R30 = RT0603BRD075K05L: RES, 5.05 k, 0.1%, 0.1 W, 0603; Manufacturer: Yageo America; CompType: Resistor; Value: 5.05k; Res_ohm: 5050; Value_Code: 5k05; Tolerance_%: 0.1; Value2: 0.1W; VDC_V: 75; TempCo: 25 ppm/C; SizeArea_mm2: 1.28; SizeX_mm: 1.6; SizeY_mm: 0.8; SizeZ_mm: 1; EIA_Code: E192; U/M: EA; AEC Category: Q200
R32 = RT0603DRE07154KL: RES, 154 k, 0.5%, 0.1 W, 0603; Manufacturer: Yageo America; CompType: Resistor; Value: 154k; Res_ohm: 154000; Tolerance_%: 0.5; Power_W: 0.1; Value2: 0.1W; VDC_V: 75; TempCo: 50 ppm/C; SizeArea_mm2: 1.28; SizeX_mm: 1.6; SizeY_mm: 0.8; SizeZ_mm: 1; EIA_Code: E192; U/M: EA; AEC Category: Q200
U1 = LMR14020SDDAR: SIMPLE SWITCHER, 4V to 40V, 2A 2.2MHz Step-Down Regulator with Low IQ, DDA0008E (SOIC-8); Manufacturer: Texas Instruments; SymbolCreator: Altium; SizeArea_mm2: 31; SizeAreaWB_mm2: 57.4; SizeX_mm: 5; SizeY_mm: 6.2; SizeZ_mm: 1.7; CompType: IC; U/M: EA
U2 = TPS43060RTER: Low Iq, Synchronous Boost Controller with Wide Input Voltage and 7.5V Gate Drive for Standard FETs, RTE0016E (WQFN-16); Alternate PartNumber: TPS43060RTET; Manufacturer: Texas Instruments; SymbolCreator: a0411947; SizeArea_mm2: 9; SizeAreaWB_mm2: 16; SizeX_mm: 3; SizeZ_mm: 0.8; CompType: IC; U/M: EA; Green_Lifecycle: Active; Green_REACh: Passed
U3 = TLV70450DBVT: Single Output LDO, 150 mA, Fixed 5 V Output, 2.5 to 24 V Input, with Ultra-Low IQ, 5-pin SOT-23 (DBV), -40 to 125 degC, Green (RoHS & no Sb/Br); Manufacturer: Texas Instruments; Alternate PartNumber: Equivalent; Accuracy(%): 2; Fixed Output Options(V): 5; Iout(Max)(A): 0.15; Iq(Typ)(mA): 0.003; SubFamily: Single Channel LDO; Vdo(Typ)(mV): 400; Vin(Max)(V): 24; Vin(Min)(V): 2.5
U4 = LM293AD: Dual Comparator, D0008A; Manufacturer: Texas Instruments; CompType: OpAmp IC
U5 = LM358AD: Dual Low Power Op Amp, D0008A; Manufacturer: Texas Instruments; CompType: OpAmp IC

## Sheet TIDA-01558_Hardware.SchDoc: Hardware
size 431 x 279 mm; Date: Not shown in title block; ApprovedBy: Not shown in title block; CheckedBy: Not shown in title block; Author: Not shown in title block; CompanyName: Not shown in title block; DrawnBy: Neha Nain; Engineer: Not shown in title block; Organization: Not shown in title block; Address1: Not shown in title block; Address2: Not shown in title block; Address3: Not shown in title block; Address4: Not shown in title block; DocumentNumber: 1; Revision: Use project parameter SCH_Rev; SheetNumber: 3; SheetTotal: 3; PageSetup: Record=PageOptions¦CenterHorizontal=True¦CenterVertical=True¦PrintScale=1.00¦XCorrection=1.00¦YCorrection=1.00¦PrintKind=0¦BorderSize=5000000¦LeftOffset=0¦BottomOffset=0¦Orientation=2¦PaperLength=1000¦PaperWidth=1000¦Scale=100¦PaperSource=15¦PrintQuality=600¦MediaType=1¦DitherType=10¦PaperKind=Letter¦PrintScaleMode=1
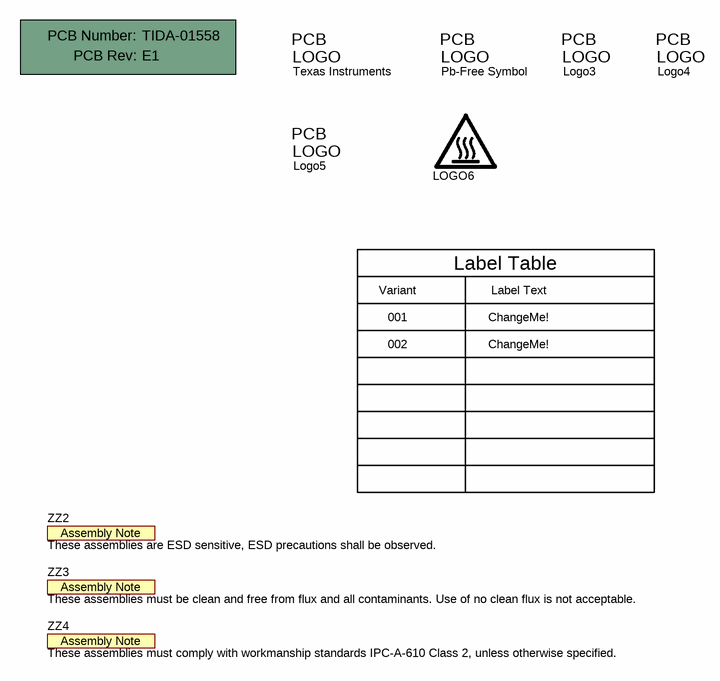
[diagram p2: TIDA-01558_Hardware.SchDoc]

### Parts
(Parts that share a designator on the sheet are numbered #1, #2 ... from top to bottom, then left to right.)
!PCB  Printed Circuit Board  (value not drawn)  (mechanical)
Logo1  Texas Instruments  [TI_Symbol_Overlay_Small]  (no BOM)
Logo2  Pb-Free Symbol  [Pb-Free_Overlay_Small]  (no BOM)
Logo3  FCC disclaimer  [FCC_disclaimer]  (value not drawn)  (no BOM)
Logo4  ESD Susceptible  [ESD_Overlay_Small]  (value not drawn)  (no BOM)
Logo5  CAUTION.  READ USER GUIDE BEFORE USE  [IEC_Caution_Small]  (value not drawn)  (no BOM)
LOGO6#3  CAUTION HOT SURFACE  [IEC_HotSurface_Small]  (value not drawn)  (no BOM)
ZZ2  These assemblies are ESD sensitive, ESD precautions shall be observed.  [AssemblyNote]  (no BOM)
ZZ3  These assemblies must be clean and free from flux and all contaminants. Use of no clean flux is not acceptable.  [AssemblyNote]  (no BOM)
ZZ4  These assemblies must comply with workmanship standards IPC-A-610 Class 2, unless otherwise specified.  [AssemblyNote]  (no BOM)

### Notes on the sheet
- Variant
- Label Table
- Label Text
- 001
- 002
- ChangeMe!

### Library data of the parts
!PCB = PCB: Manufacturer: Any; PartNumber: TIDA-01558; SymbolCreator: a0412235
Logo1 = TI_Logo: Texas Instrument Corporate Signature; SymbolCreator: codlsc
Logo2 = Pb-Free: SymbolCreator: a0412235
Logo3 = FCC_disclaimer: SymbolCreator: a0412235
Logo4 = ESD_Susceptible: ESD Susceptible Symbol; SymbolCreator: a0412235
Logo5 = IEC_Caution: IEC 61010-1 Caution Warning; SymbolCreator: a0412235
LOGO6#3 = IEC_HotSurface: as LOGO6#1 on sheet TIDA-01558_CoverSheet
ZZ2-ZZ4 = AssemblyNote: SymbolCreator: codlsc

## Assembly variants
001: all parts fitted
